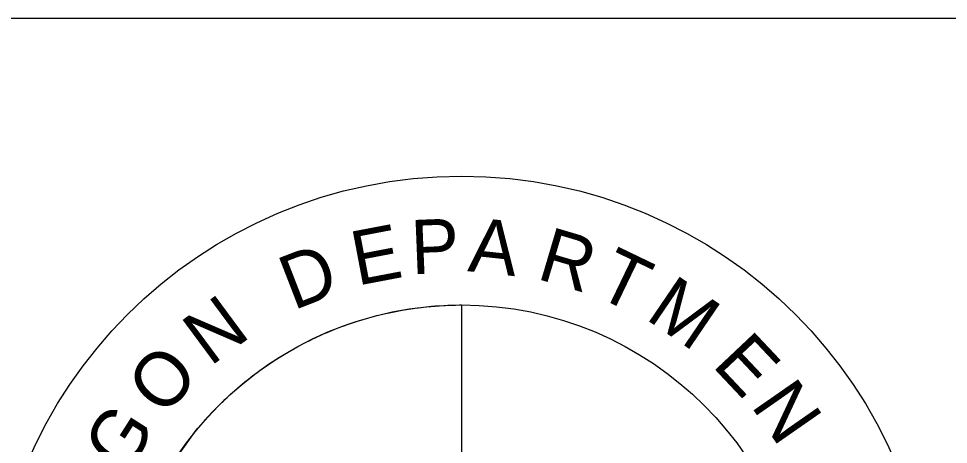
# Model space of a CAD drawing. Extents: x -1.2 to 17.3, y -1 to 2.5.
# Drawn here: x 16.5114 to 16.6099, y 1.9133 to 1.9583 of the extents above; entities that cross this region are included whole.
import ezdxf

# ---------------------------------------------------------------- set-up
doc = ezdxf.new("R2010")
doc.units = 0
doc.layers.add('P_ODOT_PLAN_Border', color=7, linetype='Continuous')
doc.layers.add('P_ODOT_PLAN_TBlock', color=7, linetype='Continuous')

msp = doc.modelspace()

# ---------------------------------------------------------------- linework, layer by layer
at = {"layer": 'P_ODOT_PLAN_Border'}
msp.add_lwpolyline([(0.041667, 0.041667), (16.625, 0.041667), (16.625, 1.958333), (0.041667, 1.958333)], close=True, dxfattribs=at)
msp.add_lwpolyline([(0.041667, 0.041667), (16.625, 0.041667), (16.625, 1.958333), (0.041667, 1.958333)], close=True, dxfattribs=at)
at = {"layer": 'P_ODOT_PLAN_TBlock'}
msp.add_lwpolyline([(16.527597, 1.911088), (16.530253, 1.914761), (16.530427, 1.914972), (16.530582, 1.915156), (16.530934, 1.915565), (16.531032, 1.915677), (16.531222, 1.915891), (16.531285, 1.915962), (16.531588, 1.916296), (16.531729, 1.916447), (16.531773, 1.916495), (16.532008, 1.916744), (16.532346, 1.917094), (16.532606, 1.917357), (16.532753, 1.917503), (16.532982, 1.917728), (16.533079, 1.917821), (16.533095, 1.917837), (16.533119, 1.917861), (16.533284, 1.918019), (16.533514, 1.918234), (16.533804, 1.918503), (16.534059, 1.918734), (16.534617, 1.919223), (16.535402, 1.919881), (16.535778, 1.920182), (16.535993, 1.920351), (16.53621, 1.920519), (16.536696, 1.920885), (16.537028, 1.921128), (16.537884, 1.921728), (16.538431, 1.922093), (16.53862, 1.922216), (16.538739, 1.922292), (16.539002, 1.922459), (16.539118, 1.922532), (16.539964, 1.923042), (16.540461, 1.923328), (16.540648, 1.923433), (16.540685, 1.923454), (16.541147, 1.923707), (16.541619, 1.923954), (16.54182, 1.924058), (16.542261, 1.924279), (16.542391, 1.924343), (16.54253, 1.92441), (16.542579, 1.924434), (16.5426, 1.924443), (16.542607, 1.924447), (16.54285, 1.924562), (16.543652, 1.924928), (16.544006, 1.925082), (16.544275, 1.925196), (16.544619, 1.925338), (16.545287, 1.925603), (16.545762, 1.925782), (16.546001, 1.925869), (16.546241, 1.925954), (16.546653, 1.926097), (16.547067, 1.926234), (16.547906, 1.926497), (16.549376, 1.926904), (16.550311, 1.927128), (16.550667, 1.927207), (16.551362, 1.927351), (16.552066, 1.92748), (16.552516, 1.927556), (16.552967, 1.927626), (16.553674, 1.927724), (16.553772, 1.927737), (16.554588, 1.927831), (16.555158, 1.927885), (16.555488, 1.927913), (16.555517, 1.927915), (16.555596, 1.927921), (16.555816, 1.927937), (16.555938, 1.927945), (16.555985, 1.927948), (16.556454, 1.927975), (16.556618, 1.927984), (16.556884, 1.927995), (16.557393, 1.928013), (16.557711, 1.928019), (16.558121, 1.928024), (16.558267, 1.928024), (16.558333, 1.928024), (16.55834, 1.908308)], dxfattribs=at)
for radius in [0.05, 0.036358]:
    msp.add_circle((16.558333, 1.891667), radius, dxfattribs=at)

# ---------------------------------------------------------------- texts
for s, rotation, p in [('E', 10.79088, (16.547284, 1.930058)), ('P', 2.30865, (16.553068, 1.931267)), ('A', 353.90454, (16.558912, 1.931612)), ('R', 343.43789, (16.566159, 1.930842)), ('D', 21.21066, (16.540523, 1.927426)), ('T', 334.27595, (16.572297, 1.929096)), ('M', 325.77028, (16.577679, 1.926619)), ('N', 36.51883, (16.531714, 1.921455)), ('E', 313.3114, (16.584764, 1.921622)), ('O', 47.07924, (16.526706, 1.916072)), ('N', 304.82916, (16.588894, 1.917396)), ('G', 57.37401, (16.522853, 1.910027))]:
    msp.add_text(s, height=0.005739, rotation=rotation, dxfattribs=at).set_placement(p)

doc.saveas('drawing.dxf')
